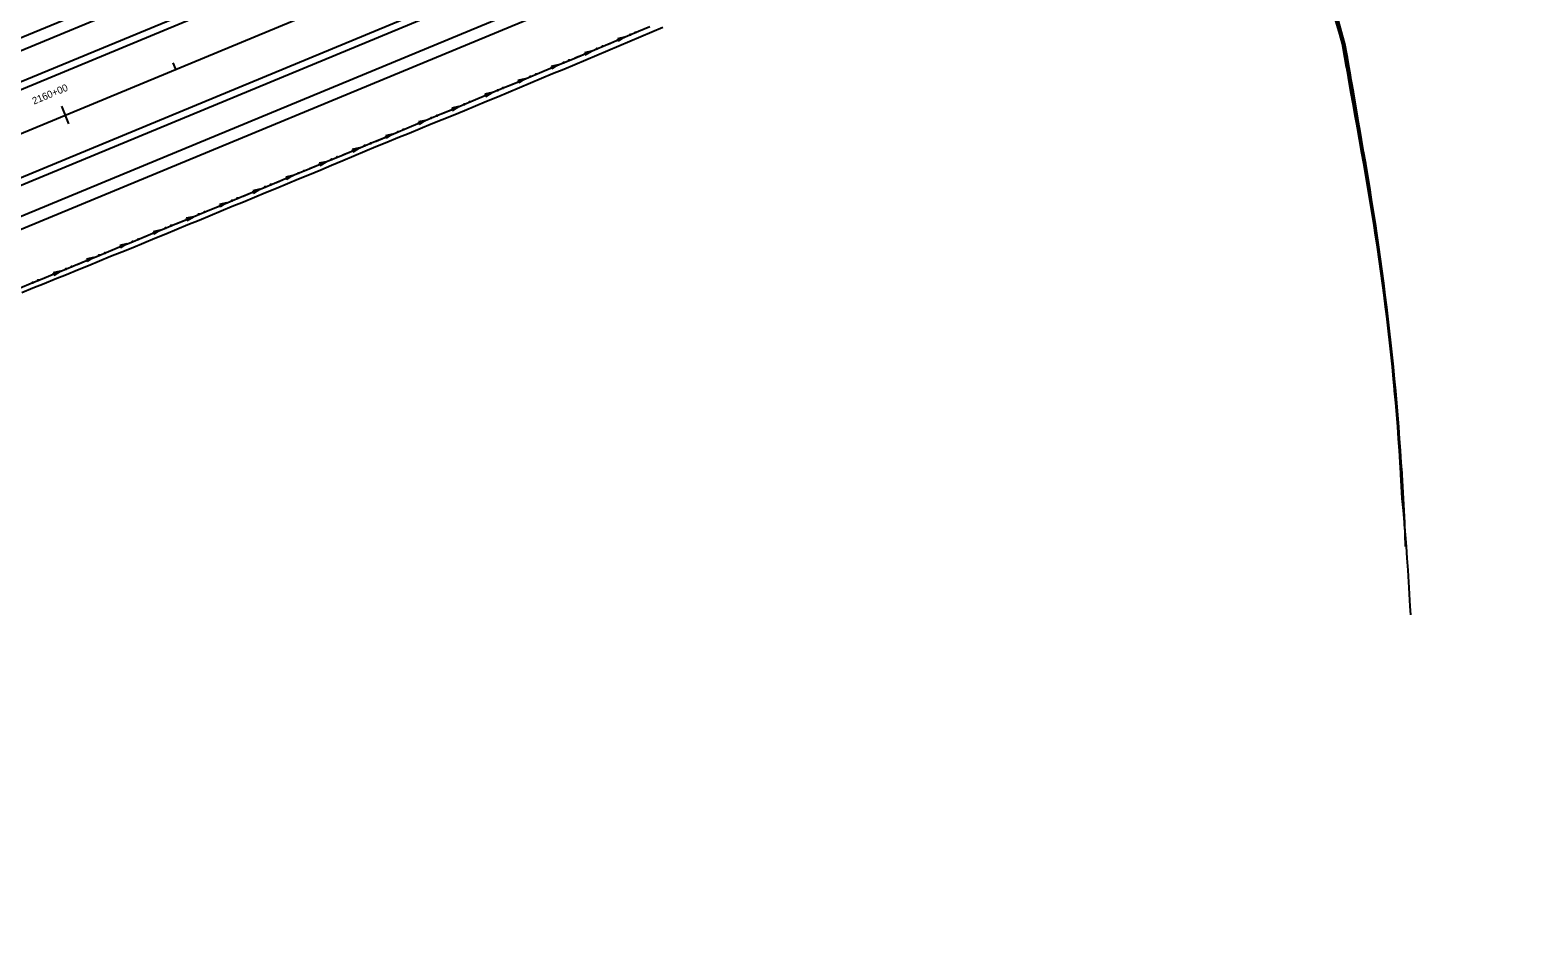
# Model space of a CAD drawing. Extents: x 1611108 to 1749517, y 619561 to 797725.
# Drawn here: x 1721752 to 1723013, y 767471 to 768235 of the extents above; entities that cross this region are included whole.
import ezdxf

# ---------------------------------------------------------------- set-up
doc = ezdxf.new("R2010")
doc.units = 0
for name, color, linetype in [('R_Ditch', 7, 'Continuous'), ('R_Horz Alg', 7, 'Continuous'), ('R_Horz Alg Stationing', 7, 'Continuous'), ('R_Proposed Const Limits', 7, 'Continuous'), ('R_Proposed Road', 7, 'Continuous')]:
    doc.layers.add(name, color=color, linetype=linetype)

msp = doc.modelspace()

# ---------------------------------------------------------------- linework, layer by layer
at = {"layer": 'R_Ditch'}
for p, q in [((1722249.1, 768229.5), (1722243.2, 768228.2)), ((1722243.2, 768228.2), (1722244, 768226.2)), ((1722244, 768226.2), (1722249.1, 768229.5)), ((1722221.4, 768217.9), (1722215.5, 768216.5)), ((1722215.5, 768216.5), (1722216.3, 768214.6)), ((1722216.3, 768214.6), (1722221.4, 768217.9)), ((1722193.7, 768206.3), (1722187.8, 768204.9)), ((1722187.8, 768204.9), (1722188.6, 768203)), ((1722188.6, 768203), (1722193.7, 768206.3)), ((1722166, 768194.6), (1722160, 768193.3)), ((1722160, 768193.3), (1722160.9, 768191.4)), ((1722160.9, 768191.4), (1722166, 768194.6)), ((1722138.3, 768183.1), (1722132.3, 768181.7)), ((1722132.3, 768181.7), (1722133.2, 768179.8)), ((1722133.2, 768179.8), (1722138.3, 768183.1)), ((1722110.6, 768171.5), (1722104.6, 768170.2)), ((1722104.6, 768170.2), (1722105.4, 768168.2)), ((1722105.4, 768168.2), (1722110.6, 768171.5)), ((1722082.8, 768159.9), (1722076.9, 768158.6)), ((1722076.9, 768158.6), (1722077.7, 768156.6)), ((1722077.7, 768156.6), (1722082.8, 768159.9)), ((1722055.1, 768148.4), (1722049.2, 768147.1)), ((1722049.2, 768147.1), (1722050, 768145.1)), ((1722050, 768145.1), (1722055.1, 768148.4)), ((1722027.4, 768136.9), (1722021.4, 768135.5)), ((1722021.4, 768135.5), (1722022.2, 768133.6)), ((1722022.2, 768133.6), (1722027.4, 768136.9)), ((1721999.6, 768125.3), (1721993.7, 768124)), ((1721993.7, 768124), (1721994.5, 768122.1)), ((1721994.5, 768122.1), (1721999.6, 768125.3)), ((1721944.1, 768102.4), (1721938.2, 768101.1)), ((1721939, 768099.1), (1721944.1, 768102.4)), ((1721971.9, 768113.9), (1721965.9, 768112.5)), ((1721965.9, 768112.5), (1721966.7, 768110.6)), ((1721966.7, 768110.6), (1721971.9, 768113.9)), ((1721916.4, 768090.9), (1721910.4, 768089.6)), ((1721910.4, 768089.6), (1721911.2, 768087.6)), ((1721911.2, 768087.6), (1721916.4, 768090.9)), ((1721938.2, 768101.1), (1721939, 768099.1)), ((1721888.6, 768079.4), (1721882.6, 768078.1)), ((1721882.6, 768078.1), (1721883.4, 768076.2)), ((1721883.4, 768076.2), (1721888.6, 768079.4)), ((1721860.8, 768068), (1721854.9, 768066.7)), ((1721854.9, 768066.7), (1721855.7, 768064.7)), ((1721855.7, 768064.7), (1721860.8, 768068)), ((1721833, 768056.6), (1721827.1, 768055.3)), ((1721827.1, 768055.3), (1721827.9, 768053.3)), ((1721827.9, 768053.3), (1721833, 768056.6)), ((1721805.2, 768045.2), (1721799.3, 768043.9)), ((1721799.3, 768043.9), (1721800.1, 768041.9)), ((1721800.1, 768041.9), (1721805.2, 768045.2)), ((1721777.4, 768033.8), (1721771.5, 768032.5)), ((1721771.5, 768032.5), (1721772.3, 768030.5)), ((1721772.3, 768030.5), (1721777.4, 768033.8))]:
    msp.add_line(p, q, dxfattribs=at)
for points in [[(1722899, 767863.9), (1722898.3, 767873.9), (1722897.5, 767883.9), (1722896.8, 767893.9), (1722896, 767903.9), (1722895.1, 767913.9), (1722894.2, 767923.9), (1722893.3, 767933.9), (1722892.3, 767943.9), (1722891.2, 767953.9), (1722890.2, 767963.9), (1722889.1, 767973.9), (1722887.9, 767983.9), (1722886.7, 767993.9), (1722885.5, 768003.9), (1722884.2, 768013.9), (1722882.8, 768023.9), (1722881.5, 768033.9), (1722880.1, 768043.9), (1722878.6, 768053.9), (1722877.1, 768063.9), (1722875.6, 768073.9), (1722874, 768083.8), (1722872.3, 768093.8), (1722870.7, 768103.8), (1722869, 768113.8), (1722867.2, 768123.8), (1722865.4, 768133.8), (1722863.6, 768143.8), (1722861.9, 768153.8), (1722861.1, 768158.1), (1722860.1, 768163.8), (1722858.3, 768173.8), (1722856.5, 768183.8), (1722855, 768192.4), (1722854.7, 768193.8), (1722854.1, 768197.6), (1722853, 768203.8), (1722852.6, 768205.8), (1722852, 768209.1), (1722852, 768209.1), (1722851.4, 768212.5), (1722851.2, 768213.8), (1722851.1, 768214), (1722849.3, 768223.8), (1722846.5, 768233.8), (1722843.8, 768243.2)], [(1722906.5, 767746.5), (1722906.1, 767753.8), (1722905.5, 767763.8), (1722905.2, 767769.3), (1722904.9, 767773.8), (1722904.3, 767783.8), (1722903.6, 767793.8), (1722902.8, 767803.8), (1722902, 767813.8), (1722901.3, 767821.8), (1722901.2, 767823.8), (1722900.3, 767833.8), (1722899.4, 767843.8), (1722898.8, 767853.8), (1722898.3, 767863.8), (1722898.2, 767865.1), (1722897.7, 767873.8), (1722897, 767883.8), (1722896.3, 767893.8), (1722895.6, 767903.8), (1722894.8, 767913.8), (1722893.9, 767923.8), (1722893, 767933.8), (1722892.9, 767935), (1722892.1, 767943.8), (1722891.2, 767953.5), (1722891.1, 767953.8), (1722890.1, 767963.8), (1722889, 767973.8), (1722887.9, 767983.8), (1722886.8, 767993.8), (1722885.6, 768003.8), (1722884.3, 768013.8), (1722883, 768023.8), (1722881.7, 768033.8), (1722880.3, 768043.8), (1722878.8, 768053.8), (1722877.3, 768063.8), (1722875.8, 768073.8), (1722874.2, 768083.8), (1722872.6, 768093.8), (1722870.9, 768103.8), (1722869.2, 768113.8), (1722867.5, 768123.8), (1722865.8, 768133.8), (1722864.1, 768143.8), (1722862.4, 768153.8), (1722861.7, 768158.1), (1722860.8, 768163.8), (1722859.1, 768173.8), (1722857.4, 768183.8), (1722855.9, 768192.3), (1722855.7, 768193.8), (1722855, 768197.6), (1722854, 768203.8), (1722853.6, 768205.7), (1722853.1, 768209), (1722853.1, 768209.1), (1722852.5, 768212.5), (1722852.3, 768213.8), (1722852.2, 768214), (1722850.5, 768223.8), (1722847.7, 768233.8), (1722845.2, 768243.1)], [(1722902.2, 767803.8), (1722901.8, 767813.8), (1722901.4, 767823.8), (1722900.9, 767833.8), (1722900.4, 767843.8), (1722899.9, 767853.8), (1722899.3, 767863.8), (1722899.2, 767865.1), (1722898.6, 767873.8), (1722897.9, 767883.8), (1722897.2, 767893.8), (1722896.5, 767903.8), (1722895.6, 767913.8), (1722894.8, 767923.8), (1722893.9, 767933.8), (1722893, 767943.8), (1722892, 767953.5), (1722892, 767953.8), (1722891, 767963.8), (1722889.9, 767973.8), (1722888.8, 767983.8), (1722887.6, 767993.8), (1722886.5, 768003.8), (1722885.2, 768013.8), (1722883.9, 768023.8), (1722882.6, 768033.8), (1722881.3, 768043.8), (1722879.9, 768053.8), (1722878.4, 768063.8), (1722876.9, 768073.8), (1722875.4, 768083.8), (1722873.8, 768093.8), (1722872.2, 768103.8), (1722870.5, 768113.8), (1722868.8, 768123.8), (1722867.1, 768133.8), (1722865.4, 768143.8), (1722863.7, 768153.8), (1722862.9, 768158.1), (1722862, 768163.8), (1722860.2, 768173.8), (1722858.5, 768183.8), (1722857, 768192.3), (1722856.8, 768193.8), (1722856.1, 768197.6), (1722855.1, 768203.8), (1722854.7, 768205.7), (1722854.2, 768209), (1722854.2, 768209.1), (1722853.6, 768212.5), (1722853.3, 768213.8), (1722853.3, 768214), (1722851.5, 768223.8), (1722848.7, 768233.8), (1722846.1, 768243.1)], [(1721743.7, 768020), (1721752.9, 768023.7), (1721762.2, 768027.5), (1721771.4, 768031.3), (1721780.7, 768035.1), (1721789.9, 768038.9), (1721799.2, 768042.7), (1721808.4, 768046.5), (1721817.7, 768050.3), (1721826.9, 768054.1), (1721836.2, 768057.9), (1721845.4, 768061.7), (1721854.7, 768065.5), (1721863.9, 768069.3), (1721873.2, 768073.1), (1721882.4, 768076.9), (1721891.7, 768080.7), (1721900.9, 768084.5), (1721910.2, 768088.3), (1721919.4, 768092.2), (1721928.6, 768096), (1721937.9, 768099.8), (1721947.1, 768103.6), (1721956.4, 768107.4), (1721965.6, 768111.3), (1721974.9, 768115.1), (1721984.1, 768118.9), (1721993.3, 768122.7), (1722002.6, 768126.6), (1722011.8, 768130.4), (1722021, 768134.2), (1722030.3, 768138.1), (1722039.5, 768141.9), (1722048.7, 768145.7), (1722058, 768149.6), (1722067.2, 768153.4), (1722076.4, 768157.3), (1722085.7, 768161.1), (1722094.9, 768165), (1722104.1, 768168.8), (1722113.4, 768172.7), (1722122.6, 768176.5), (1722131.8, 768180.4), (1722141, 768184.2), (1722150.3, 768188.1), (1722159.5, 768191.9), (1722168.7, 768195.8), (1722177.9, 768199.7), (1722187.2, 768203.5), (1722196.4, 768207.4), (1722205.6, 768211.2), (1722214.8, 768215.1), (1722224.1, 768219), (1722233.3, 768222.9), (1722242.5, 768226.7), (1722251.7, 768230.6), (1722260.9, 768234.5), (1722270.2, 768238.4)], [(1722235.3, 768223.7), (1722242.5, 768226.7), (1722249.1, 768229.5)], [(1722262.9, 768235.3), (1722263, 768235.3)], [(1722207.6, 768212.1), (1722214.8, 768215.1), (1722221.4, 768217.9)], [(1722235.2, 768223.7), (1722235.3, 768223.7)], [(1722179.9, 768200.5), (1722187.2, 768203.5), (1722193.7, 768206.3)], [(1722207.5, 768212.1), (1722207.6, 768212.1)], [(1722152.2, 768188.9), (1722159.5, 768191.9), (1722166, 768194.6)], [(1722179.8, 768200.4), (1722179.9, 768200.5)], [(1722124.4, 768177.3), (1722131.8, 768180.4), (1722138.3, 768183.1)], [(1722124.4, 768177.3), (1722124.4, 768177.3)], [(1722152.1, 768188.8), (1722152.2, 768188.9)], [(1722096.7, 768165.7), (1722104.1, 768168.8), (1722110.6, 768171.5)], [(1722096.7, 768165.7), (1722096.7, 768165.7)], [(1722069, 768154.2), (1722076.4, 768157.3), (1722082.8, 768159.9)], [(1722069, 768154.2), (1722069, 768154.2)], [(1722041.2, 768142.6), (1722041.3, 768142.6)], [(1722041.3, 768142.6), (1722048.7, 768145.7), (1722055.1, 768148.4)], [(1722013.5, 768131.1), (1722021, 768134.2), (1722027.4, 768136.9)], [(1722013.5, 768131.1), (1722013.5, 768131.1)], [(1721985.7, 768119.6), (1721985.8, 768119.6)], [(1721985.8, 768119.6), (1721993.3, 768122.7), (1721999.6, 768125.3)], [(1721930.3, 768096.6), (1721937.9, 768099.8), (1721944.1, 768102.4)], [(1721958, 768108.1), (1721965.6, 768111.3), (1721971.9, 768113.9)], [(1721958, 768108.1), (1721958, 768108.1)], [(1721902.5, 768085.2), (1721910.2, 768088.3), (1721916.4, 768090.9)], [(1721930.2, 768096.6), (1721930.3, 768096.6)], [(1721874.7, 768073.7), (1721882.4, 768076.9), (1721888.6, 768079.4)], [(1721902.4, 768085.2), (1721902.5, 768085.2)], [(1721846.9, 768062.3), (1721854.7, 768065.5), (1721860.8, 768068)], [(1721874.7, 768073.7), (1721874.7, 768073.7)], [(1721819.1, 768050.9), (1721826.9, 768054.1), (1721833, 768056.6)], [(1721846.9, 768062.3), (1721846.9, 768062.3)], [(1721791.3, 768039.5), (1721791.4, 768039.5)], [(1721791.4, 768039.5), (1721799.2, 768042.7), (1721805.2, 768045.2)], [(1721819.1, 768050.9), (1721819.1, 768050.9)], [(1721763.5, 768028.1), (1721763.6, 768028.1)], [(1721763.6, 768028.1), (1721771.4, 768031.3), (1721777.4, 768033.8)]]:
    msp.add_lwpolyline(points, dxfattribs=at)
for centre in [(1722253.7, 768231.5), (1722258.3, 768233.4), (1722226, 768219.8), (1722230.6, 768221.8), (1722198.3, 768208.2), (1722202.9, 768210.2), (1722170.6, 768196.6), (1722175.2, 768198.5), (1722142.9, 768185), (1722147.5, 768187), (1722115.2, 768173.4), (1722119.8, 768175.4), (1722064.3, 768152.3), (1722087.4, 768161.9), (1722092.1, 768163.8), (1722036.6, 768140.7), (1722059.7, 768150.3), (1722004.2, 768127.3), (1722008.9, 768129.2), (1722032, 768138.8), (1721976.5, 768115.8), (1721981.1, 768117.7), (1721948.7, 768104.3), (1721953.4, 768106.2), (1721921, 768092.8), (1721925.6, 768094.8), (1721893.2, 768081.4), (1721897.8, 768083.3), (1721865.4, 768069.9), (1721870.1, 768071.9), (1721837.6, 768058.5), (1721842.3, 768060.4), (1721809.9, 768047.1), (1721814.5, 768049), (1721758.9, 768026.2), (1721782.1, 768035.7), (1721786.7, 768037.6), (1721754.3, 768024.3)]:
    msp.add_circle(centre, 0.375, dxfattribs=at)
at = {"layer": 'R_Horz Alg'}
msp.add_line((1715964.9, 765755.1), (1723860.6, 769025.6), dxfattribs=at)
at = {"layer": 'R_Horz Alg Stationing'}
for points in [[(1721871.4, 768208.1), (1721873.7, 768202.6)], [(1721778.2, 768171.7), (1721784.3, 768156.9)]]:
    msp.add_lwpolyline(points, dxfattribs=at)
at = {"layer": 'R_Proposed Const Limits'}
msp.add_lwpolyline([(1721745.3, 768016.1), (1721754.5, 768019.8), (1721763.8, 768023.5), (1721773.1, 768027.3), (1721782.4, 768031), (1721791.6, 768034.9), (1721800.8, 768038.7), (1721810.1, 768042.5), (1721819.3, 768046.3), (1721828.7, 768049.9), (1721837.9, 768053.6), (1721847.2, 768057.5), (1721856.4, 768061.3), (1721865.7, 768065.1), (1721874.9, 768068.9), (1721884.1, 768072.8), (1721893.4, 768076.6), (1721902.6, 768080.4), (1721911.9, 768084.2), (1721921.1, 768088.1), (1721930.4, 768091.9), (1721939.6, 768095.6), (1721948.8, 768099.5), (1721958.1, 768103.3), (1721967.3, 768107.1), (1721976.6, 768110.9), (1721985.8, 768114.7), (1721995.1, 768118.5), (1722004.2, 768122.5), (1722013.5, 768126.4), (1722022.7, 768130.2), (1722031.9, 768134.1), (1722041.1, 768138), (1722050.4, 768141.8), (1722059.6, 768145.6), (1722068.9, 768149.3), (1722078.2, 768153.1), (1722087.4, 768156.9), (1722096.7, 768160.6), (1722105.9, 768164.4), (1722115.2, 768168.3), (1722124.4, 768172.1), (1722133.7, 768175.9), (1722142.9, 768179.7), (1722152.2, 768183.5), (1722161.4, 768187.4), (1722170.6, 768191.3), (1722179.8, 768195.1), (1722189, 768199), (1722198.3, 768202.8), (1722207.5, 768206.7), (1722216.7, 768210.6), (1722225.9, 768214.5), (1722235.1, 768218.3), (1722244.4, 768222.2), (1722253.6, 768226.1), (1722262.8, 768230), (1722272, 768233.9), (1722281.2, 768237.7)], dxfattribs=at)
at = {"layer": 'R_Proposed Road'}
for p, q in [((1715936.5, 765823.4), (1723832.3, 769093.9)), ((1715940.4, 765814.2), (1723836.1, 769084.7)), ((1715949.6, 765792), (1723845.3, 769062.5)), ((1715951.9, 765786.5), (1723847.6, 769057)), ((1715977.9, 765723.6), (1723873.6, 768994.2)), ((1715980.2, 765718.1), (1723875.9, 768988.6)), ((1715989.4, 765695.9), (1723885.1, 768966.5)), ((1715993.2, 765686.7), (1723888.9, 768957.2))]:
    msp.add_line(p, q, dxfattribs=at)

# ---------------------------------------------------------------- texts
at = {"layer": 'R_Horz Alg Stationing'}
msp.add_text('2160+00', height=6, rotation=22.5, dxfattribs=at).set_placement((1721755.3, 768173))

doc.saveas('drawing.dxf')
